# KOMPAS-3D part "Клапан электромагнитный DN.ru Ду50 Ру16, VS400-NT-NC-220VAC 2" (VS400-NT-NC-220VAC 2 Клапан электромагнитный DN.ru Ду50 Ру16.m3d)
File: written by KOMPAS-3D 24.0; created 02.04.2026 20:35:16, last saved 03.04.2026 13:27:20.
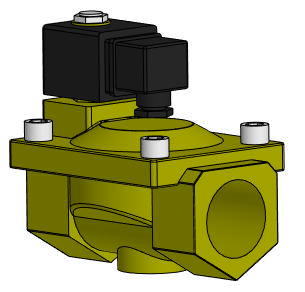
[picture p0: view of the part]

Document properties: Автор: artio; Полное имя файла: C:\Users\artio\OneDrive\Рабочий стол\Клапан электромагнитный DN.ru VS4x-xT-NC-x\VS400-NT-NC\VS400-NT-NC-220VAC 2 Клапан электромагнитный DN.ru Ду50 Ру16.m3d

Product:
- Body: Тело 1  | qty 1
    Масса: 7.119215
- Part/product: Клапан электромагнитный DN.ru Ду50 Ру16  | designation VS400-NT-NC-220VAC 2
    Масса: 3.509
    Раздел спецификации: Прочие изделия
    Примечание: D130-04666
    additional columns: ef56311e-7521-43dc-8291-0e6108b3d81d; VS400-ET-NC-220VAC 2; artio; c; Шероховатость не задана; Да

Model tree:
1. Операция без истории:1

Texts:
  VS400-NT-NC-220VAC 2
